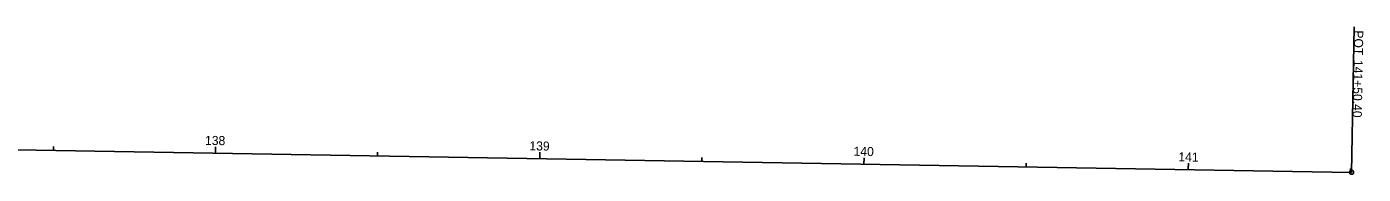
# Model space of a CAD drawing. Extents: x 2003596 to 2006888, y 572582 to 572983.
# Drawn here: x 2006475.6 to 2006887.7, y 572582.2 to 572627.8 of the extents above; entities that cross this region are included whole.
import ezdxf

# ---------------------------------------------------------------- set-up
doc = ezdxf.new("R2010")
doc.units = 0
for name, color, linetype in [('DR_X_Ditch', 7, 'Continuous'), ('PM_X_Surveyed_Line', 7, 'Continuous'), ('PV_X_COP', 7, 'Continuous'), ('RD_X_Fence', 7, 'Continuous'), ('SV_X_Top_of_Bank', 7, 'Continuous'), ('UT_X_Water_Cells', 7, 'Continuous'), ('VG_X_Tree_Line_Lt', 7, 'Continuous')]:
    doc.layers.add(name, color=color, linetype=linetype)

msp = doc.modelspace()

# ---------------------------------------------------------------- linework, layer by layer
at = {"layer": 'DR_X_Ditch'}
for p, q in [((2006483.76, 572589.51), (2006483.78, 572590.71)), ((2006533.75, 572588.67), (2006533.78, 572590.67)), ((2006583.74, 572587.82), (2006583.76, 572589.02)), ((2006633.73, 572586.98), (2006633.77, 572588.98)), ((2006683.73, 572586.14), (2006683.75, 572587.34)), ((2006733.72, 572585.3), (2006733.75, 572587.3)), ((2006783.71, 572584.46), (2006783.73, 572585.66)), ((2006833.71, 572583.62), (2006833.74, 572585.62)), ((2006883.7, 572582.78), (2006883.72, 572583.98))]:
    msp.add_line(p, q, dxfattribs=at)
at = {"layer": 'PM_X_Surveyed_Line'}
msp.add_line((2006023.62, 572597.25), (2006884.1, 572582.77), dxfattribs=at)
at = {"layer": 'PV_X_COP'}
msp.add_line((2006884.1, 572582.77), (2006884.86, 572627.76), dxfattribs=at)
msp.add_circle((2006884.1, 572582.77), 0.6, dxfattribs=at)
at = {"layer": 'RD_X_Fence'}
for p, q in [((2006533.75, 572588.67), (2006533.77, 572589.87)), ((2006633.73, 572586.98), (2006633.75, 572588.18)), ((2006733.72, 572585.3), (2006733.75, 572587.3)), ((2006833.71, 572583.62), (2006833.73, 572584.82))]:
    msp.add_line(p, q, dxfattribs=at)
at = {"layer": 'SV_X_Top_of_Bank'}
msp.add_line((2006884.1, 572582.77), (2006884.86, 572627.76), dxfattribs=at)
msp.add_circle((2006884.1, 572582.77), 0.6, dxfattribs=at)
at = {"layer": 'UT_X_Water_Cells'}
msp.add_line((2006733.72, 572585.3), (2006733.75, 572587.3), dxfattribs=at)
at = {"layer": 'VG_X_Tree_Line_Lt'}
msp.add_line((2006884.1, 572582.77), (2006884.86, 572627.76), dxfattribs=at)
msp.add_circle((2006884.1, 572582.77), 0.6, dxfattribs=at)

# ---------------------------------------------------------------- texts
at = {"layer": 'DR_X_Ditch'}
for s, p in [('138', (2006530.51, 572591.27)), ('139', (2006630.53, 572589.58)), ('140', (2006730.48, 572587.9)), ('141', (2006830.64, 572586.17))]:
    msp.add_text(s, height=2.8, rotation=359.0359, dxfattribs=at).set_placement(p)
at = {"layer": 'PV_X_COP'}
for s, p in [('POT', (2006884.89, 572626.64)), ('141+50.40', (2006884.73, 572617.51))]:
    msp.add_text(s, height=2.8, rotation=269.0359, dxfattribs=at).set_placement(p)
at = {"layer": 'RD_X_Fence'}
msp.add_text('140', height=2.8, rotation=359.0359, dxfattribs=at).set_placement((2006730.48, 572587.9))
at = {"layer": 'SV_X_Top_of_Bank'}
for s, p in [('POT', (2006884.89, 572626.64)), ('141+50.40', (2006884.73, 572617.51))]:
    msp.add_text(s, height=2.8, rotation=269.0359, dxfattribs=at).set_placement(p)
at = {"layer": 'UT_X_Water_Cells'}
msp.add_text('140', height=2.8, rotation=359.0359, dxfattribs=at).set_placement((2006730.48, 572587.9))
at = {"layer": 'VG_X_Tree_Line_Lt'}
for s, p in [('POT', (2006884.89, 572626.64)), ('141+50.40', (2006884.73, 572617.51))]:
    msp.add_text(s, height=2.8, rotation=269.0359, dxfattribs=at).set_placement(p)

doc.saveas('drawing.dxf')
